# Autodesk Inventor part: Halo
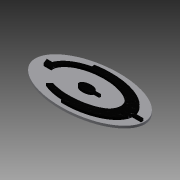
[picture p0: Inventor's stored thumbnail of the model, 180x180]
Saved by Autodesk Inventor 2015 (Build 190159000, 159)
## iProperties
Created: 2017-03
Part Number: Halo
Material: Generisch
Document SubType Name: Modeling
Designer: Andreas
Density: 1 g/cm^3
Appearance: Vorgabe
Author: Andreas
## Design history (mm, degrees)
sketch "Skizze1"
  geometry: L1 (0, 0)-(677.333, 0); L2 (677.333, 0)-(677.333, -381); L3 (677.333, -381)-(0, -381); L4 (0, -381)-(0, 0); L5 (371.139, -182.025)-(394.382, -182.025); L6 (394.382, -182.025)-(394.382, -190.006); L7 (394.382, -190.006)-(371.565, -190.006); 1 further point; 2 other entities
  constraints: 6 end point, 2 horizontal, 1 perpendicular, 6 other
  node "Bild1"
sketch "Skizze2"
  geometry: L1 (250.367, -243.752)-(235.602, -258.956); L2 (189.261, -190.533)-(155.985, -190.533); L3 (155.985, -190.533)-(146.628, -167.104); L4 (146.628, -167.104)-(170.471, -167.104); L5 (170.471, -167.104)-(171.473, -164.231); L6 (171.473, -164.231)-(173.283, -160.022); L7 (173.283, -160.022)-(176.86, -153.835); L8 (176.86, -153.835)-(180.732, -148.406); L9 (180.732, -148.406)-(185.783, -142.261); L10 (185.783, -142.261)-(191.381, -137); L11 (191.381, -137)-(197.526, -131.655); L12 (197.526, -131.655)-(202.282, -128.258); L13 (202.282, -128.258)-(204.596, -126.393); L14 (204.596, -126.393)-(209.773, -122.946); L15 (209.773, -122.946)-(213.645, -120.754); L16 (213.645, -120.754)-(218.107, -118.144); L17 (218.107, -118.144)-(224.252, -115.072); L18 (224.252, -115.072)-(229.892, -112.387); L19 (229.892, -112.387)-(233.113, -110.766); L20 (233.113, -110.766)-(241.656, -107.632); L21 (241.656, -107.632)-(247.241, -105.583); L22 (247.241, -105.583)-(252.427, -103.68); L23 (252.427, -103.68)-(256.254, -102.677); L24 (256.254, -102.677)-(262.7, -100.841); L25 (262.7, -100.841)-(266.985, -99.626); L26 (266.985, -99.626)-(271.442, -98.699); L27 (271.442, -98.699)-(271.917, -98.575); L28 (271.917, -98.575)-(272.467, -98.575); L29 (272.467, -98.575)-(270.584, -87.45); L30 (537.481, -191.23)-(575.39, -191.23); L31 (575.39, -191.23)-(575.39, -180.511); L32 (575.39, -180.511)-(537.481, -180.511); L33 (330.281, -289.334)-(328.295, -277.566); L34 (270.584, -87.45)-(273.882, -86.643); L35 (273.882, -86.643)-(279.239, -85.737); L36 (279.239, -85.737)-(286.167, -84.564); L37 (286.167, -84.564)-(294.633, -83.526); L38 (294.633, -83.526)-(303.114, -82.743); L39 (303.114, -82.743)-(310.308, -82.183); L40 (310.308, -82.183)-(317.725, -81.707); L41 (317.725, -81.707)-(327.662, -81.343); L42 (327.662, -81.343)-(338.222, -81.207); L43 (338.222, -81.207)-(348.626, -81.371); L44 (348.626, -81.371)-(358.87, -81.735); L45 (358.87, -81.735)-(368.975, -82.407); L46 (368.975, -82.407)-(381.039, -83.526); L47 (381.039, -83.526)-(389.52, -84.618); L48 (389.52, -84.618)-(397.945, -85.934); L49 (397.945, -85.934)-(406.426, -87.45); L50 (406.426, -87.45)-(415.13, -89.32); L51 (415.13, -89.32)-(422.492, -91.056); L52 (422.492, -91.056)-(430.581, -93.239); L53 (430.581, -93.239)-(441.469, -96.542); L54 (441.469, -96.542)-(449.166, -98.699); L55 (449.166, -98.699)-(457.647, -102.056); L56 (457.647, -102.056)-(464.841, -104.967); L57 (464.841, -104.967)-(471.978, -108.298); L58 (471.978, -108.298)-(480.655, -112.552); L59 (480.655, -112.552)-(487.989, -116.608); L60 (487.989, -116.608)-(492.719, -119.449); L61 (492.719, -119.449)-(500.36, -124.67); L62 (500.36, -124.67)-(505.818, -128.87); L63 (505.818, -128.87)-(510.784, -132.952); L64 (510.784, -132.952)-(515.438, -137.472)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; 71 further points
  constraints: 18 end point, 7 horizontal, 2 perpendicular, 1 parallel, 112 other
extrude "Extrusion1" new body sketch "Skizze2" distance "d3" = 10; taper "d4" = 0 deg
extrude "Extrusion2" join sketch "Skizze1" distance "d6" = 10; taper "d7" = 0 deg
sketch "Skizze3" dims "d8" = 235, "d9" = 125
  geometry: 2 further points; 1 other entity
  constraints: 2 other
extrude "Extrusion3" join sketch "Skizze3" distance "d10" = 10; taper "d11" = 0 deg
node "Volumenkörper1"
